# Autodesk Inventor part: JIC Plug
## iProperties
Category: Hydraulics
Title: JIC Plug
Author: QBZ
Shininess: 27.0
PropertySet Name: _Private Model Information
Created: 2001-03
Part Number: 900599-6S
Material: Steel, Mild
Document SubType Name: Modeling
Designer: QBZ
Description: JIC Plug -6
Catalog Web Link: http://www.aeroquip.com
Control State: 0
Master: False
Checked Out: False
PropertySet Name: Design Tracking Control
Density: 0.0
Volumn: 0.0
Area: 0.0
PropertySet Name: Model Information
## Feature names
1. Revolution1
2. Hole1
3. Revolution2
